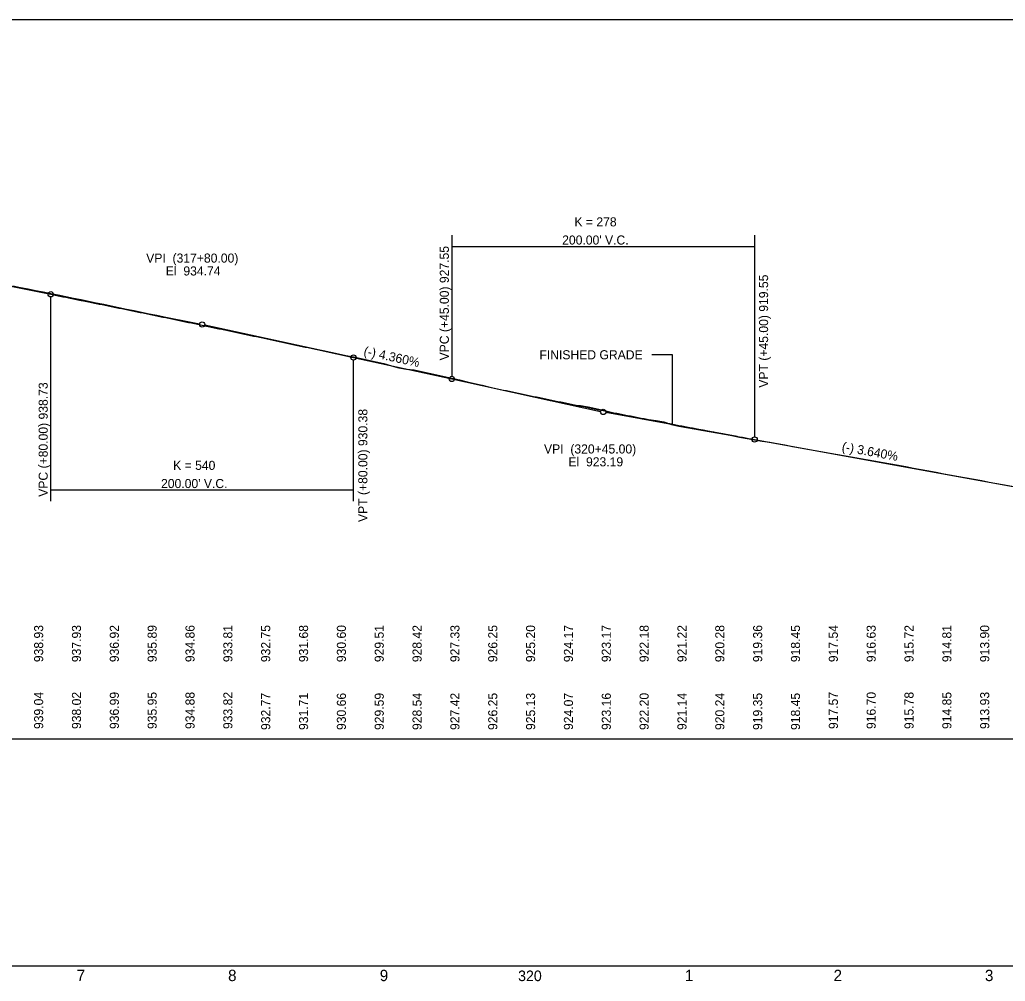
# Model space of a CAD drawing. Extents: x 4180 to 16997695, y 4 to 12629821.
# Drawn here: x 16984079 to 16984730, y 12628452 to 12629087 of the extents above; entities that cross this region are included whole.
import ezdxf

# ---------------------------------------------------------------- set-up
doc = ezdxf.new("R2010")
doc.units = 0
for name, color, linetype in [('Default', 7, 'Continuous'), ('RD_DDB_GradeTX', 7, 'Continuous'), ('RD_DDB_PI', 7, 'Continuous'), ('RD_DDB_PR_Tx', 7, 'Continuous'), ('RD_DDB_Profile_EX', 7, 'Continuous'), ('RD_DDB_Profile_PR', 7, 'Continuous'), ('RD_DDB_StaTX', 7, 'Continuous'), ('RD_DDB_StripGrade', 7, 'Continuous'), ('RD_DDB_StripGrade_PR', 7, 'Continuous'), ('RD_DDB_VCLbl', 7, 'Continuous'), ('RD_GPK_Profile_Cell', 7, 'Continuous')]:
    doc.layers.add(name, color=color, linetype=linetype)

msp = doc.modelspace()

# ---------------------------------------------------------------- linework, layer by layer
at = {"layer": 'Default'}
msp.add_lwpolyline([(16983719.88, 12628611.61), (16985219.88, 12628611.61), (16985219.88, 12629086.61), (16983719.88, 12629086.61)], close=True, dxfattribs=at)
at = {"layer": 'RD_DDB_PI'}
for p, q in [((16984111.61, 12628902.92), (16984198.16, 12628885.66)), ((16984287.81, 12628866.15), (16984201.58, 12628884.94)), ((16984376.94, 12628846.71), (16984463.17, 12628827.92)), ((16984553.42, 12628811.43), (16984466.6, 12628827.23))]:
    msp.add_line(p, q, dxfattribs=at)
for centre in [(16984199.88, 12628885.32), (16984464.88, 12628827.54)]:
    msp.add_circle(centre, 1.75, dxfattribs=at)
at = {"layer": 'RD_DDB_PR_Tx'}
for p, q in [((16984496.88, 12628865.52), (16984510.3, 12628865.52)), ((16984510.3, 12628865.52), (16984510.3, 12628819.55))]:
    msp.add_line(p, q, dxfattribs=at)
at = {"layer": 'RD_DDB_Profile_EX'}
for points in [[(16984074.88, 12628910.77), (16984079.88, 12628909.77), (16984084.88, 12628908.78), (16984089.88, 12628907.8), (16984094.88, 12628906.82), (16984099.88, 12628905.84), (16984104.88, 12628904.81), (16984109.88, 12628903.78), (16984114.88, 12628902.74), (16984119.88, 12628901.71)], [(16984119.88, 12628901.71), (16984124.88, 12628900.69), (16984129.88, 12628899.66), (16984134.88, 12628898.64), (16984139.88, 12628897.61), (16984144.88, 12628896.58), (16984149.88, 12628895.54), (16984154.88, 12628894.5), (16984159.88, 12628893.46), (16984164.88, 12628892.42), (16984169.88, 12628891.37), (16984174.88, 12628890.3), (16984179.88, 12628889.23), (16984184.88, 12628888.17), (16984189.88, 12628887.1), (16984194.88, 12628886.03), (16984199.88, 12628884.97), (16984204.88, 12628883.9), (16984209.88, 12628882.84), (16984219.88, 12628880.7)], [(16984219.88, 12628880.7), (16984224.88, 12628879.64), (16984229.88, 12628878.6), (16984234.88, 12628877.55), (16984239.88, 12628876.51), (16984244.88, 12628875.45), (16984249.88, 12628874.39), (16984254.88, 12628873.33), (16984259.88, 12628872.27), (16984264.88, 12628871.2), (16984269.88, 12628870.14), (16984274.88, 12628869.1), (16984279.88, 12628868.05), (16984284.88, 12628867), (16984289.88, 12628865.95), (16984294.88, 12628864.89), (16984299.88, 12628863.84), (16984304.88, 12628862.78), (16984309.88, 12628861.71), (16984314.88, 12628860.64), (16984319.88, 12628859.54), (16984324.88, 12628858.09), (16984329.88, 12628856.64), (16984334.88, 12628855.83), (16984339.88, 12628855.4), (16984344.88, 12628854.29), (16984349.88, 12628853.19), (16984354.88, 12628852.08), (16984359.88, 12628850.95), (16984364.88, 12628849.82), (16984369.88, 12628848.69), (16984374.88, 12628847.51), (16984379.88, 12628846.33), (16984384.88, 12628845.15), (16984389.88, 12628844.01), (16984394.88, 12628842.87), (16984399.88, 12628841.73), (16984404.88, 12628840.59), (16984409.88, 12628839.48), (16984414.88, 12628838.37), (16984419.88, 12628837.25), (16984424.88, 12628836.23), (16984429.88, 12628835.2), (16984434.88, 12628834.13), (16984439.88, 12628833.05), (16984444.88, 12628831.97), (16984449.88, 12628831.8), (16984454.88, 12628830.83), (16984459.88, 12628829.85), (16984464.88, 12628828.63), (16984469.88, 12628827.39), (16984474.88, 12628826.15), (16984479.88, 12628824.91), (16984484.88, 12628824.09), (16984489.88, 12628823.36), (16984494.88, 12628822.63), (16984499.88, 12628821.9), (16984504.88, 12628820.98), (16984509.88, 12628819.21), (16984514.88, 12628818.25), (16984519.88, 12628817.31), (16984524.88, 12628816.37), (16984529.88, 12628815.46), (16984534.88, 12628814.57), (16984539.88, 12628813.69), (16984544.88, 12628812.8), (16984549.88, 12628811.9), (16984554.88, 12628811), (16984559.88, 12628810.1), (16984564.88, 12628809.2), (16984569.88, 12628808.34), (16984574.88, 12628807.49), (16984579.88, 12628806.64), (16984584.88, 12628805.74), (16984589.88, 12628804.81), (16984594.88, 12628803.89), (16984599.88, 12628802.97), (16984604.88, 12628802.08), (16984609.88, 12628801.19), (16984614.88, 12628800.32), (16984619.88, 12628799.44)], [(16984619.88, 12628799.44), (16984624.88, 12628798.57), (16984629.88, 12628797.71), (16984634.88, 12628796.85), (16984639.88, 12628795.99), (16984644.88, 12628795.13), (16984649.88, 12628794.22), (16984654.88, 12628793.3), (16984659.88, 12628792.38), (16984664.88, 12628791.46), (16984669.88, 12628790.51), (16984674.88, 12628789.56), (16984679.88, 12628788.62), (16984684.88, 12628787.7), (16984689.88, 12628786.78), (16984694.88, 12628785.87), (16984699.88, 12628784.95), (16984704.88, 12628784.04), (16984709.88, 12628783.12), (16984714.88, 12628782.19), (16984719.88, 12628781.26), (16984724.88, 12628780.35), (16984729.88, 12628779.48), (16984734.88, 12628778.62)]]:
    msp.add_lwpolyline(points, dxfattribs=at)
at = {"layer": 'RD_DDB_Profile_PR'}
for p, q in [((16983504.88, 12629023.97), (16984099.88, 12628905.27)), ((16984299.88, 12628863.52), (16984364.88, 12628849.35)), ((16984564.88, 12628809.34), (16984749.88, 12628775.67))]:
    msp.add_line(p, q, dxfattribs=at)
for points in [[(16984099.88, 12628905.27), (16984103.88, 12628904.47), (16984107.88, 12628903.67), (16984111.88, 12628902.87), (16984115.88, 12628902.06), (16984119.88, 12628901.26), (16984123.88, 12628900.45), (16984127.88, 12628899.64), (16984131.88, 12628898.83), (16984135.88, 12628898.02), (16984139.88, 12628897.21), (16984143.88, 12628896.4), (16984147.88, 12628895.58), (16984151.88, 12628894.77), (16984155.88, 12628893.95), (16984159.88, 12628893.13), (16984163.88, 12628892.31), (16984167.88, 12628891.49), (16984171.88, 12628890.66), (16984175.88, 12628889.84), (16984179.88, 12628889.01), (16984183.88, 12628888.18), (16984187.88, 12628887.35), (16984191.88, 12628886.52), (16984195.88, 12628885.69), (16984199.88, 12628884.85), (16984203.88, 12628884.02), (16984207.88, 12628883.18), (16984211.88, 12628882.34), (16984215.88, 12628881.5), (16984219.88, 12628880.66), (16984223.88, 12628879.82), (16984227.88, 12628878.97), (16984231.88, 12628878.13), (16984235.88, 12628877.28), (16984239.88, 12628876.43), (16984243.88, 12628875.58), (16984247.88, 12628874.73), (16984251.88, 12628873.87), (16984255.88, 12628873.02), (16984259.88, 12628872.16), (16984263.88, 12628871.3), (16984267.88, 12628870.44), (16984271.88, 12628869.58), (16984275.88, 12628868.72), (16984279.88, 12628867.86), (16984283.88, 12628866.99), (16984287.88, 12628866.12), (16984291.88, 12628865.26), (16984295.88, 12628864.39), (16984299.88, 12628863.52)], [(16984364.88, 12628849.35), (16984368.88, 12628848.47), (16984372.88, 12628847.61), (16984376.88, 12628846.74), (16984380.88, 12628845.88), (16984384.88, 12628845.02), (16984388.88, 12628844.16), (16984392.88, 12628843.31), (16984396.88, 12628842.46), (16984400.88, 12628841.61), (16984404.88, 12628840.77), (16984408.88, 12628839.93), (16984412.88, 12628839.09), (16984416.88, 12628838.25), (16984420.88, 12628837.42), (16984424.88, 12628836.59), (16984428.88, 12628835.76), (16984432.88, 12628834.94), (16984436.88, 12628834.12), (16984440.88, 12628833.3), (16984444.88, 12628832.48), (16984448.88, 12628831.67), (16984452.88, 12628830.86), (16984456.88, 12628830.05), (16984460.88, 12628829.25), (16984464.88, 12628828.44), (16984468.88, 12628827.65), (16984472.88, 12628826.85), (16984476.88, 12628826.06), (16984480.88, 12628825.27), (16984484.88, 12628824.48), (16984488.88, 12628823.7), (16984492.88, 12628822.92), (16984496.88, 12628822.14), (16984500.88, 12628821.36), (16984504.88, 12628820.59), (16984508.88, 12628819.82), (16984512.88, 12628819.05), (16984516.88, 12628818.29), (16984520.88, 12628817.53), (16984524.88, 12628816.77), (16984528.88, 12628816.01), (16984532.88, 12628815.26), (16984536.88, 12628814.51), (16984540.88, 12628813.76), (16984544.88, 12628813.02), (16984548.88, 12628812.28), (16984552.88, 12628811.54), (16984556.88, 12628810.81), (16984560.88, 12628810.07), (16984564.88, 12628809.34)]]:
    msp.add_spline(points, degree=3, dxfattribs=at)
at = {"layer": 'RD_DDB_VCLbl'}
for p, q in [((16984364.88, 12628944.35), (16984364.88, 12628851.1)), ((16984564.88, 12628944.35), (16984564.88, 12628811.09)), ((16984364.88, 12628936.85), (16984564.88, 12628936.85)), ((16984099.88, 12628768.52), (16984099.88, 12628903.52)), ((16984299.88, 12628768.52), (16984299.88, 12628861.77)), ((16984099.88, 12628776.02), (16984299.88, 12628776.02))]:
    msp.add_line(p, q, dxfattribs=at)
for centre in [(16984099.88, 12628905.27), (16984299.88, 12628863.52), (16984364.88, 12628849.35), (16984564.88, 12628809.34)]:
    msp.add_circle(centre, 1.75, dxfattribs=at)
at = {"layer": 'RD_GPK_Profile_Cell'}
msp.add_line((16972619.88, 12628461.61), (16997196.51, 12628461.61), dxfattribs=at)

# ---------------------------------------------------------------- texts
at = {"layer": 'RD_DDB_GradeTX'}
for s, rotation, p in [('(-) 4.360%', 347.70171, (16984306.23, 12628865.08)), ('(-) 3.640%', 349.685, (16984622.15, 12628801.86))]:
    msp.add_text(s, height=6, rotation=rotation, dxfattribs=at).set_placement(p)
at = {"layer": 'RD_DDB_PI'}
for s, p in [('VPI  (317+80.00)', (16984162.94, 12628926.17)), ('El  934.74', (16984175.9, 12628917.67)), ('VPI  (320+45.00)', (16984425.75, 12628800.1)), ('El  923.19', (16984441.9, 12628791.6))]:
    msp.add_text(s, height=6, dxfattribs=at).set_placement(p)
at = {"layer": 'RD_DDB_PR_Tx'}
msp.add_text('FINISHED GRADE', height=6, dxfattribs=at).set_placement((16984422.7, 12628862.32))
at = {"layer": 'RD_DDB_StaTX'}
for s, height, p in [('7', 7.5, (16984117, 12628451.61)), ('8', 7.5, (16984217.03, 12628451.61)), ('9', 7.5, (16984317.23, 12628451.61)), ('320', 7, (16984408.63, 12628451.61)), ('1', 7.5, (16984518.87, 12628451.61)), ('2', 7.5, (16984617.03, 12628451.61)), ('3', 7.5, (16984717.03, 12628451.61))]:
    msp.add_text(s, height=height, dxfattribs=at).set_placement(p)
at = {"layer": 'RD_DDB_StripGrade'}
for s, p in [('939.04', (16984094.88, 12628618.11)), ('938.02', (16984119.88, 12628618.11)), ('936.99', (16984144.88, 12628618.11)), ('935.95', (16984169.88, 12628618.11)), ('934.88', (16984194.88, 12628618.11)), ('933.82', (16984219.88, 12628618.11)), ('932.77', (16984244.88, 12628617.47)), ('931.71', (16984269.88, 12628617.47)), ('930.66', (16984294.88, 12628617.47)), ('929.59', (16984319.88, 12628617.47)), ('928.54', (16984344.88, 12628617.47)), ('927.42', (16984369.88, 12628617.47)), ('926.25', (16984394.88, 12628617.47)), ('925.13', (16984419.88, 12628617.47)), ('924.07', (16984444.88, 12628617.47)), ('923.16', (16984469.88, 12628617.47)), ('922.20', (16984494.88, 12628617.47)), ('921.14', (16984519.88, 12628617.47)), ('920.24', (16984544.88, 12628617.47)), ('919.35', (16984569.88, 12628617.47)), ('918.45', (16984594.88, 12628617.47)), ('917.57', (16984619.88, 12628618.11)), ('916.70', (16984644.88, 12628618.11)), ('915.78', (16984669.88, 12628618.11)), ('914.85', (16984694.88, 12628618.11)), ('913.93', (16984719.88, 12628618.11))]:
    msp.add_text(s, height=6, rotation=90, dxfattribs=at).set_placement(p)
at = {"layer": 'RD_DDB_StripGrade_PR'}
for s, p in [('938.93', (16984094.88, 12628662.28)), ('937.93', (16984119.88, 12628662.28)), ('936.92', (16984144.88, 12628662.28)), ('935.89', (16984169.88, 12628662.28)), ('934.86', (16984194.88, 12628662.28)), ('933.81', (16984219.88, 12628662.28)), ('932.75', (16984244.88, 12628662.28)), ('931.68', (16984269.88, 12628662.28)), ('930.60', (16984294.88, 12628662.28)), ('929.51', (16984319.88, 12628662.28)), ('928.42', (16984344.88, 12628662.28)), ('927.33', (16984369.88, 12628662.28)), ('926.25', (16984394.88, 12628662.28)), ('925.20', (16984419.88, 12628662.28)), ('924.17', (16984444.88, 12628662.28)), ('923.17', (16984469.88, 12628662.28)), ('922.18', (16984494.88, 12628662.28)), ('921.22', (16984519.88, 12628662.28)), ('920.28', (16984544.88, 12628662.28)), ('919.36', (16984569.88, 12628662.28)), ('918.45', (16984594.88, 12628662.28)), ('917.54', (16984619.88, 12628662.28)), ('916.63', (16984644.88, 12628662.28)), ('915.72', (16984669.88, 12628662.28)), ('914.81', (16984694.88, 12628662.28)), ('913.90', (16984719.88, 12628662.28))]:
    msp.add_text(s, height=6, rotation=90, dxfattribs=at).set_placement(p)
at = {"layer": 'RD_DDB_VCLbl'}
for s, p in [('K = 278', (16984445.83, 12628950.1)), ("200.00' V.C.", (16984437.74, 12628938.1)), ('K = 540', (16984180.75, 12628789.27)), ("200.00' V.C.", (16984172.74, 12628777.27))]:
    msp.add_text(s, height=6, dxfattribs=at).set_placement(p)
for s, p in [('VPC (+45.00) 927.55', (16984362.88, 12628861.57)), ('VPT (+45.00) 919.55', (16984573.79, 12628843.57)), ('VPC (+80.00) 938.73', (16984097.88, 12628771.5)), ('VPT (+80.00) 930.38', (16984309.06, 12628754.84))]:
    msp.add_text(s, height=6, rotation=90, dxfattribs=at).set_placement(p)

doc.saveas('drawing.dxf')
